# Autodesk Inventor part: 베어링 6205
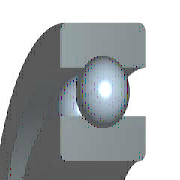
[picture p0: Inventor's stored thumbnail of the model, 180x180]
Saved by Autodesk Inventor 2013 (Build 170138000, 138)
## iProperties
IsCustomPart: 1
Company: 한국ATC센터
Created: 2014-11
Part Number: 베어링 6205
Material: Steel, Mild
Description: 깊은 그루브 볼 베어링
Document SubType Name: Modeling
Standard: KS B 2023
Designer: KYOUNG IL JANG
Standards Organization: KS
Language: ko-KR
Size Designation: 6205 - 25 x 52 x 15
Categories: <MemberInstance><Categories><Category DisplayName="샤프트 부품" InternalName="7f7aeb1f-a693-4053-b835-cee3144e0d98" Mnemonic="SHFT"><Category DisplayName="베어링" Inter
Density: 7.86 g/cm^3
Mass: 129.543 g
Surface Area: 107.326 cm^2
Volume: 16.4813 cm^3
Author: KYOUNG IL JANG
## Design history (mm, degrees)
revolve "본체" stored, may be unused: angle "d6" = 90 deg
revolve "볼" stored, may be unused: angle "d7" = 90 deg
pattern_circular "IDS_ARRAYBALL[SIMPL:T]" dims angle "d3" = 360 deg
body "Solid1"
sketch "스케치" dims "d0" = 7.02 (= -0.26 x WD + 0.26 x BD)
  geometry: L1 (3.99, 19.25)-(11.01, 19.25); L2 (7.5, 19.25)-(7.5, 15.74); L3 (7.5, 19.25)-(7.5, 22.76); L4 (4.892, 16.901)-(0, 16.901); L5 (0, 12.5)-(15, 12.5); L6 (4.892, 21.599)-(0, 21.599); L7 (0, 26)-(15, 26); L8 (15, 12.5)-(15, 16.901); L9 (10.108, 16.901)-(15, 16.901); L10 (10.108, 21.599)-(15, 21.599); L11 (15, 26)-(15, 21.599); L12 (-1.4, 0)-(8.4, 0) reference; L13 (0, -0.3)-(0, 5.3) reference
  constraints: 22 end point, 4 point on line, 2 collinear, 2 perpendicular, 2 symmetric about line, 1 midpoint, 1 parallel, 14 other
  dimensions: "d9" = 25 diameter of L5 L12 (= WD); "d11" = 52 diameter of L7 L12 (= BD); "d12" = 15 distance between parallel lines of L8 L13 (= KB); "d13" = 33.802 diameter of L9 L12 (= 0.326 x BD + 0.674 x WD)
fillet "모깎기1" dims "d1" = 1 (= KRS)
other parameters: "WD" = 25 [user parameter; used in 5 equation terms], "BD" = 52 [user parameter; used in 5 equation terms], "KB" = 15 [user parameter; used in 1 equation term], "KRS" = 1 [user parameter; used in 1 equation term], "d4" = 0, "d5" = 0, "d8" = 0, "d14" = 0, "d15" = 0, "BBA" = 0 [user parameter], "BC0" = 7800000 [user parameter], "BC" = 1.4e+07 [user parameter], "BR" = 26 (= 0.5 x BD) [user parameter], "WR" = 12.5 (= 0.5 x WD) [user parameter]
